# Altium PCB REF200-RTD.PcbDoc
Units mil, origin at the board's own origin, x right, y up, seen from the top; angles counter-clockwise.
Board outline 2500 x 2000 mil, 2 copper layers (Top Layer, Bottom Layer); 30 components, 11 nets, 59 pads, 9 vias.
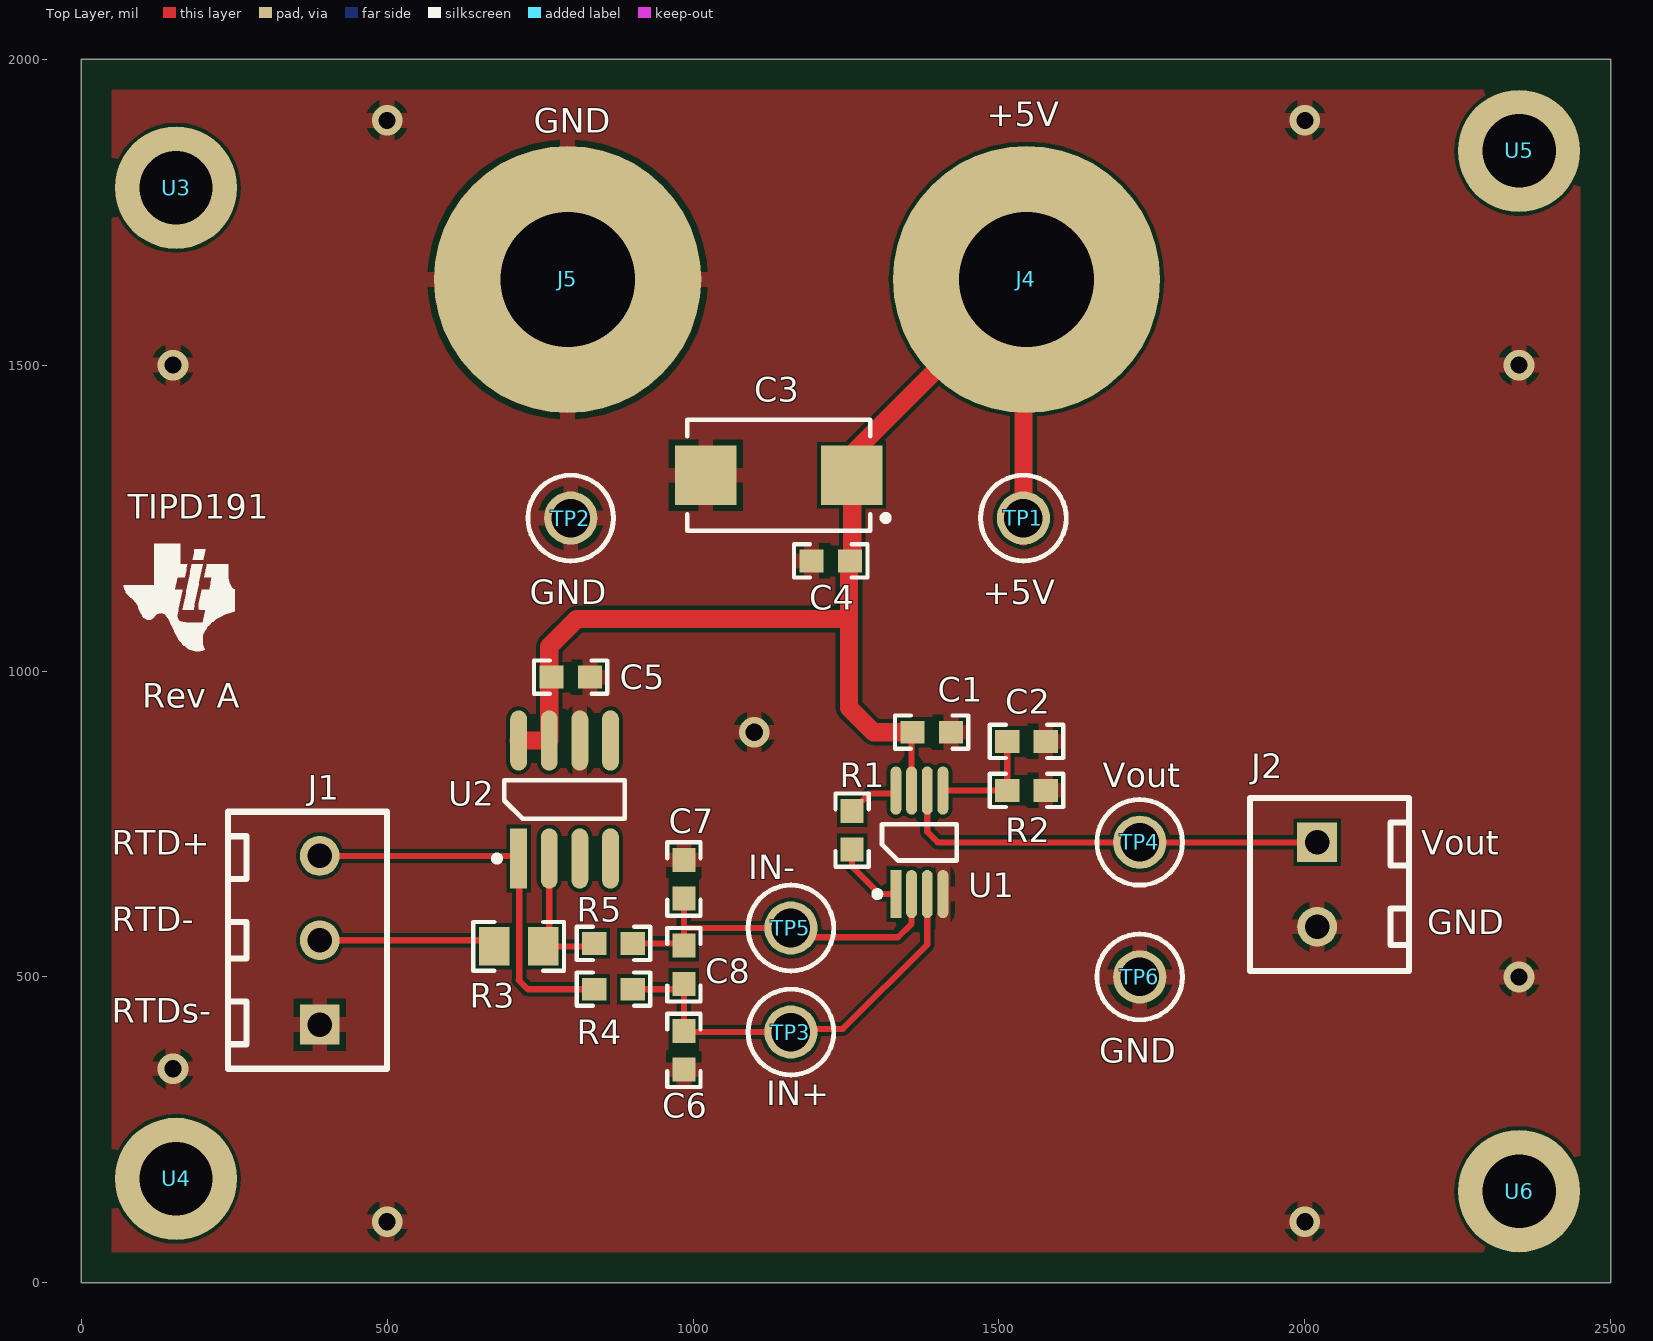
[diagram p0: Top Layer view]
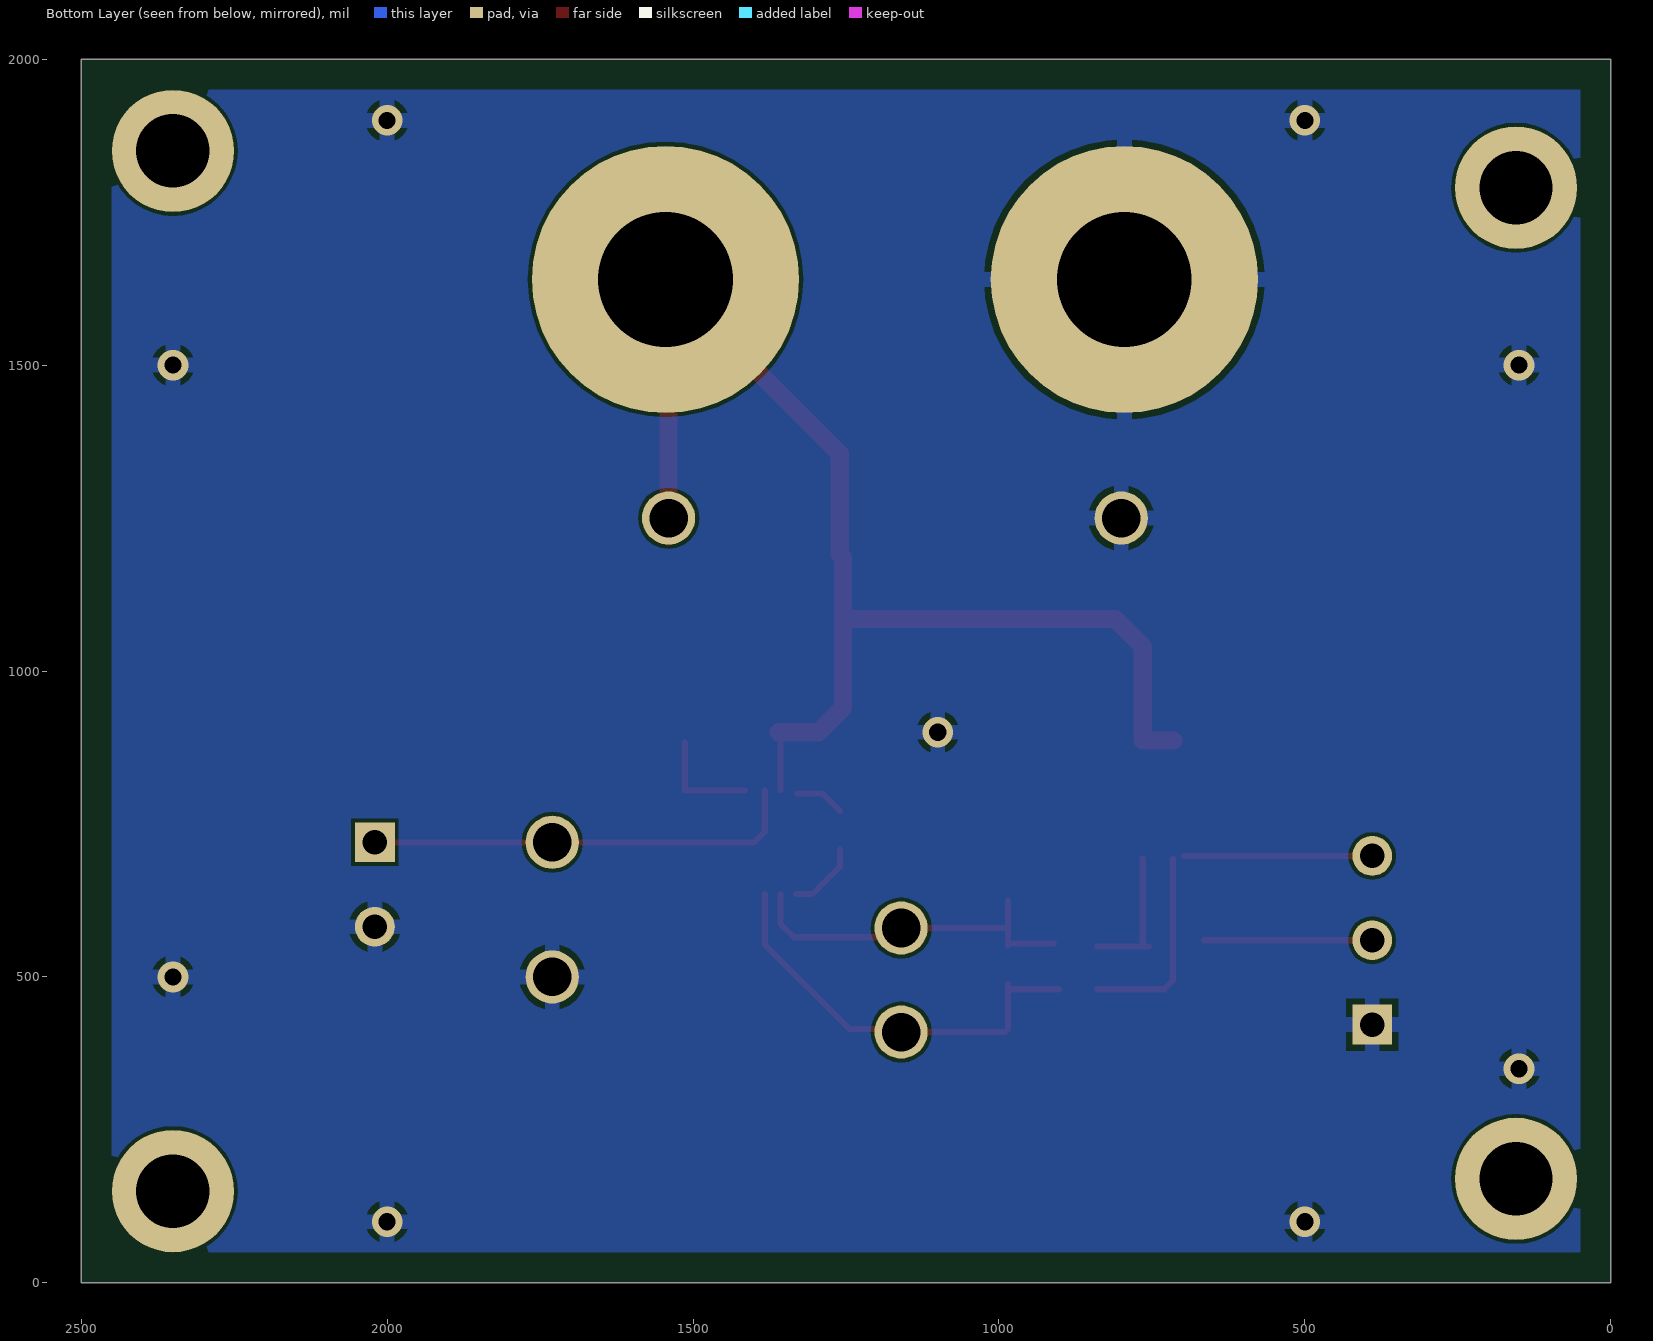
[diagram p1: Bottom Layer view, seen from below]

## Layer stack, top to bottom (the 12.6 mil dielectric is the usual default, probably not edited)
Top Layer: signal copper 1.4
Dielectric: core 12.6, FR-4, Dk 4.8
Bottom Layer: signal copper 1.4

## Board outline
0,2000 0,0 2500,0 2500,2000 0,2000

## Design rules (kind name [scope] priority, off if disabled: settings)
AssemblyTestPointUsage [All] p1 off:
AssemblyTestpoint [All] p1 off: testpointundercomponent=TRUE minsize=40 maxsize=100 preferedsize=60 minholesize=0 maxholesize=40 preferedholesize=32 testpointgrid=1 usegrid=TRUE gridtolerance=0.01 allowsidetop=TRUE allowsidebottom=TRUE
Clearance [All] p1: gap=6
ComponentClearance [All] p1 off: gap=10 collisioncheckmode=3 verticalgap=10 showdistances=FALSE
DiffPairsRouting [All] p1 off: maxlimit=10 minlimit=10 mostfreqgap=10 maxuncoupledlength=500
FabricationTestPointUsage TestPointUsage [All] p1 off: valid=0 allowmultiple=FALSE
FabricationTestpoint Testpoint [All] p1 off: side=3 testpointundercomponent=TRUE minsize=40 maxsize=100 preferedsize=60 minholesize=0 maxholesize=40 preferedholesize=32 testpointgrid=1 allowsidetop=TRUE allowsidebottom=TRUE usegrid=TRUE gridtolerance=0.01
FanoutControl Fanout_BGA [IsBGA] p1 off: bgadir=Out bgaviamode=Centered fanoutstyle=Auto fanoutdirection=Alternating viagrid=1 // Fanout_BGA (Default Rule)
FanoutControl Fanout_LCC [IsLCC] p2 off: bgadir=Out bgaviamode=Centered fanoutstyle=Auto fanoutdirection=Alternating viagrid=1 // Fanout_LCC (Default Rule)
FanoutControl Fanout_SOIC [IsSOIC] p3 off: bgadir=Out bgaviamode=Centered fanoutstyle=Auto fanoutdirection=Alternating viagrid=1 // Fanout_SOIC (Default Rule)
FanoutControl Fanout_Small [(CompPinCount < 5)] p4 off: bgadir=Out bgaviamode=Centered fanoutstyle=Auto fanoutdirection=OutThenIn viagrid=1 // Fanout_Small (Default Rule)
FanoutControl Fanout_Default [All] p5 off: bgadir=Out bgaviamode=Centered fanoutstyle=Auto fanoutdirection=Alternating viagrid=1 // Fanout_Default (Default Rule)
Height [All] p1 off: minheight=0 maxheight=1000 prefheight=500
HoleSize [All] p1: absolutevalues=TRUE maxlimit=400 minlimit=15 maxpercent=80.000 minpercent=20.000
HoleToHoleClearance [All] p1: gap=8 allowstackedmicrovias=TRUE
LayerPairs [All] p1 off: enforce=FALSE
MinimumSolderMaskSliver [All] p1: minsoldermaskwidth=4
PolygonConnect PolygonConnect_1 [InPadClass('GNDVia')] p1: connectstyle=Direct reliefconductorwidth=10 reliefentries=4 polygonreliefangle="90 Angle" airgapwidth=10
PolygonConnect [All] p2: connectstyle=Relief reliefconductorwidth=25 reliefentries=4 polygonreliefangle="90 Angle" airgapwidth=10
RoutingVias [All] p1: holewidth=15 width=25 viastyle="Through Hole" minholewidth=15 minwidth=25 maxholewidth=400 maxwidth=500
SilkToSilkClearance [All] p1: silktosilkclearance=5
SilkscreenOverComponentPads [IsPad] p1: minsilkscreentomaskgap=5
SolderMaskExpansion [All] p1: expansion=2
Width Width_1 [InNetClass('Power')] p1: maxlimit=100 minlimit=10 preferedwidth=30 minimp=50.000000 maximp=50.000000 favimp=50.000000
Width [All] p2: maxlimit=100 minlimit=6 preferedwidth=10
10 further rules are at their usual default settings.

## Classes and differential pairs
net class Power: +5V

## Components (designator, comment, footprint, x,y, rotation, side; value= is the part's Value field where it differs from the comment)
C1 "06033D104KAT2A" 0603 1390,900 r0 top
C2 "GRM1885C1H201JA01D" 0603 1545,885 r0 top
C3 "293D106X9050E2TE3" 7343-43 1140,1320 r180 top
C4 "06033D104KAT2A" 0603 1225,1180 r180 top
C5 "06033D104KAT2A" 0603 800,990 r0 top
C6 "06031C102JAT2A" 0603 985,380 r90 top
C7 "06031C102JAT2A" 0603 985,660 r90 top
C8 "06031C103JAT2A" 0603 985,520 r90 top
J1 "ED555/3DS" "Terminal Block 3.5mm 3 pos" 390,560 r180 top
J2 "Used in BOM report" "TERMINAL BLOCK 3.5MM 2 POS" 2020,720 r0 top
J4 "+5V" "JACK NON-INSULATED .218\"" 1545,1640 r90 top
J5 "GND" "JACK NON-INSULATED .218\"" 795,1640 r90 top
R1 "CPF0603B2K0E" 0603 1260,740 r270 top
R2 "CRCW0603698KFKEA" 0603 1545,805 r180 top
R3 "CRCW080578R7FKEA" 0805_HV 715,550 r0 top
R4 "CPF0603B100KE" 0603 870,480 r0 top
R5 "CPF0603B100KE" 0603 870,555 r0 top
TIPD191 "SE AC Coupled" TI_Symbol_Overlay_Small 160,1120 r0 top
TP1 "+5V" Keystone5005 1540,1250 r90 top
TP2 "GND" Keystone5006 800,1250 r90 top
TP3 "IN+" Keystone5005 1160,410 r90 top
TP4 "Vout" Keystone5005 1730,720 r90 top
TP5 "IN-" Keystone5005 1160,580 r90 top
TP6 "GND" Keystone5006 1730,500 r90 top
U1 "INA326EA" "VSSOP-8 (DGK) low density" 1370,720 r90 top
U2 "Used in BOM report" "SOIC-8 (D) low density" 790,790 r90 top
U3 "Standoff" MHOLE1 155,1790 r0 top
U4 "Standoff" MHOLE1 155,170 r0 top
U5 "Standoff" MHOLE1 2350,1850 r0 top
U6 "Standoff" MHOLE1 2350,150 r0 top

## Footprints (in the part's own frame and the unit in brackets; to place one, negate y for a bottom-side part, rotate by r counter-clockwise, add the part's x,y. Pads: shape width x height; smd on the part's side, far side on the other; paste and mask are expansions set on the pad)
0603 [mm] "0603 from SM-752 data"
  rect 1x0.95 smd: 1(-0.8,0) 2(0.8,0)
  silkscreen extent -1.52,-0.69 1.52,0.69, body extent -0.87,-0.47 0.87,0.47, height 0.85
0805_HV [mil] "0805 with 30mil clearance between pads"
  rect 50x63 smd: 1(-40,0) 2(40,0)
  silkscreen extent -74,-40 74,40, body extent -43,-29 43,29, height 43
7343-43 [mm] "Medium density IPC based on Kemet T495 series"
  rect 2.55x2.45 smd: 1(-3.025,0) 2(3.025,0)
  silkscreen extent -4.56,-2.3 3.8,2.3, body extent -3.8,-2.3 3.8,2.3, height 4.3
"JACK NON-INSULATED .218\"" [mil] "JACK NON-INSULATED .218\""
  round 437 hole 220: 1(0,0)
Keystone5005 [mil] "Keystone Compact loops"
  round 87 hole 63: 1(0,0)
  silkscreen extent -70,-70 70,70, body extent -63,-63 62,63, height 225
Keystone5006 [mil] "Keystone Compact loops"
  round 87 hole 63: 1(0,0)
  silkscreen extent -70,-70 70,70, body extent -63,-63 62,63, height 225
MHOLE1 [mil]
  round 200 hole 120: 0(0,0)
"SOIC-8 (D) low density" [mm] "SOIC, 8-Leads, Body 4.9x3.9mm, Pitch 1.27mm, IPC Low Density"
  rect 2.5x0.7 smd: 1(-2.45,1.905)
  oval 2.5x0.7 smd: 2(-2.45,0.635) 3(-2.45,-0.635) 4(-2.45,-1.905) 5(2.45,-1.905) 6(2.45,-0.635) 7(2.45,0.635) 8(2.45,1.905)
  silkscreen extent -2.57,-2.5 0.8,2.93, body extent -2,-2.5 2,2.5, height 1.75
"TERMINAL BLOCK 3.5MM 2 POS" [mil]
  rect 65x65 hole 40: 1(0,0)
  round 65 hole 40: 2(0,-137.8)
  silkscreen extent -110,-210 150,72
"Terminal Block 3.5mm 3 pos" [mil] "TERMINAL BLOCK 3.5MM 3POS PCB"
  rect 65x65 hole 40: 1(0,137.8)
  round 65 hole 40: 2(0,0) 3(0,-137.8)
  silkscreen extent -110,-210 150,210
TI_Symbol_Overlay_Small [mil]
  silkscreen extent -90,-88 91,88
"VSSOP-8 (DGK) low density" [mm] "TSOP, 8-Leads, Body 3x3mm, Pitch 0.65mm, IPC Low Density"
  rect 2x0.45 smd: 1(-2.15,0.975)
  oval 2x0.45 smd: 2(-2.15,0.325) 3(-2.15,-0.325) 4(-2.15,-0.975) 5(2.15,-0.975) 6(2.15,-0.325) 7(2.15,0.325) 8(2.15,0.975)
  silkscreen extent -2.27,-1.55 0.75,1.87, body extent -1.55,-1.55 1.55,1.55, height 1.1

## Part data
C1 C4 C5: "CAP, CERM, 0.1 µF, 25 V, +/- 10%, X5R, 0603"
C2: "CAP, CERM, 200 pF, 50 V, +/- 5%, C0G/NP0, 0603"
C3: "CAP, TA, 10 µF, 50 V, +/- 10%, 0.8 ohm, SMD"
C6 C7: "CAP, CERM, 1000 pF, 100 V, +/- 5%, X7R, 0603"
C8: "CAP, CERM, 0.01 µF, 100 V, +/- 5%, X7R, 0603"
J1: library part "Screw Terminal, 3 Pos, 3.5mm Spacing, Through Hole"
J2: library part "Screw Terminal, 2 pos, 3.5mm, ED555/2DS"
J4 J5: library part "Banana Jack, Solder", "JACK NON-INSULATED .218\""
R1: "RES, 2.00 k, 0.1%, 0.063 W, 0603"
R2: "RES, 698 k, 1%, 0.1 W, 0603"
R3: "RES, 78.7, 1%, 0.125 W, 0805"
R4 R5: "RES, 100 k, 0.1%, 0.063 W, 0603"
TIPD191: library part TI_Logo, "Texas Instrument Corporate Signature"
TP1 TP3 TP4 TP5: library part 5005, "Test Point, TH, Compact, Red"
TP2 TP6: library part 5006, "Test Point, TH, Compact, Black"
U1: "Precision, Rail-to-Rail I/O  INSTRUMENTATION AMPLIFIER, VSSOP-8"
U2: library part REF200
U3 U4 U5 U6: library part "Standoff, 1\", 4-40, Alum, F-F", "STANDOFF HEX 4-40THR ALUM 1\"L"

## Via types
v1: diameter 50, hole 28, Top Layer to Bottom Layer, 9 vias

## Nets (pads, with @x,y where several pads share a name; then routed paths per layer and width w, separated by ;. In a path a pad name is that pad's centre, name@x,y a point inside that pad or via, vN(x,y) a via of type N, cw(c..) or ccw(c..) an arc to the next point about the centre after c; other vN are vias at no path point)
+5V: C1.1 C3.1 C4.1 C5.1 J4.1 TP1.1 U1.7 U2.7 U2.8 | length 2058.5
  Top Layer w10: U1.7 C1.1@1357.2,892.8
  Top Layer w30: U2.8 U2.7@761.46,886.46 ; U2.7 765,1040 810,1085 1255,1085 ; C1.1@1360,900 C1.1 1295,900 1255,940 1255,1085 ; TP1.1@1540,1220 J4.1@1540,1540 ; J4.1 1260,1355 1260,1190 1255,1185 1255,1085
GND: C1.2 C2.2 C3.2 C4.2 C5.2 C6.1 C7.2 J1.1 J2.2 J5.1 R2.1 TP2.1 TP6.1 U1.4 U2.6
  other v1: 500,100 2000,100 150,350 2350,500 1100,900 150,1500 2350,1500 500,1900 2000,1900
NetC2_1: C2.1 R2.2 U1.5 | length 177
  Top Layer w10: U1.5@1415,805 R2.2 C2.1@1513.5,883.5
NetC6_2: C6.2 C8.1 R4.2 TP3.1 U1.3 | length 689.4
  Top Layer w10: R4.2 C8.1@985,480 ; C6.2@985,415 C8.1@985,480 ; C8.1 C8.1@985,480 ; C6.2@990,410 TP3.1 ; TP3.1@1160,415 1245,415 1382.8,552.8 U1.3
NetC7_1: C7.1 C8.2 R5.2 TP5.1 U1.2 | length 553.1
  Top Layer w10: R5.2@910,555 985,555 C8.2 ; C8.2@985,560 C7.1@985,625 ; 990,580 TP5.1 ; TP5.1@1175,565 1335,565 1357.2,587.2 U1.2
NetJ1_2: J1.2 R3.1 | length 280
  Top Layer w10: J1.2@385,560 J1.2 R3.1@665,560
NetJ1_3: J1.3 R4.1 U2.1 | length 639
  Top Layer w10: J1.3 697.8,697.8 ; U2.1 716,692.54 716,495 715,495 730,480 R4.1 R4.1@840,480
NetJ2_1: J2.1 TP4.1 U1.6 | length 711.8
  Top Layer w10: U1.6 1382.8,737.2 1400,720 TP4.1 J2.1
NetR1_1: R1.1 U1.8 | length 81.8
  Top Layer w10: R1.1 1288.5,800 U1.8@1330,800
NetR1_2: R1.2 U1.1 | length 112
  Top Layer w10: R1.2 1260,680 1300,640 ; 1304.65,635.35 U1.1
NetR3_2: R3.2 R5.1 U2.2 | length 223.5
  Top Layer w10: R3.2 R5.1@840,550 ; R3.2@765,555 U2.2
pads on no net: U2.3 U2.4 U2.5 U3.0 U4.0 U5.0 U6.0

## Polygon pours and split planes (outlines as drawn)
GND on Bottom Layer "Bottom Layer-No Net" (solid, remove dead copper, pour order 10): 50,1950 50,50 2450,50 2450,1950 50,1950
GND on Top Layer "Top Layer-No Net" (solid, remove dead copper, pour order 15): 50,1950 50,50 2450,50 2450,1950 50,1950

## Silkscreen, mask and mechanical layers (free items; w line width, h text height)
Top Overlay:
  text "Rev A" at 100,940 h40
  text "RTD+" at 50,700 h40
  text "Vout" at 2190,700 h40
  text "RTD-" at 50,575 h40
  text "GND" at 2200,570 h40
  text "RTDs-" at 50,425 h40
